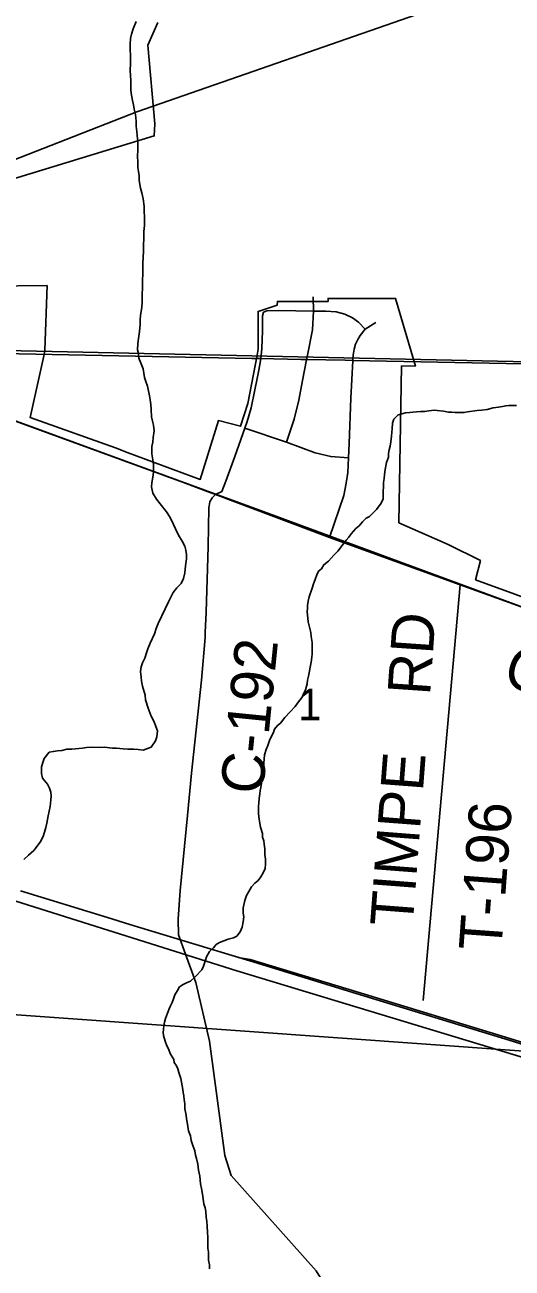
# Model space of a CAD drawing. Extents: x 36.7 to 70.7, y 0 to 22.
# Drawn here: x 40.424 to 41.074, y 18.615 to 20.274 of the extents above; entities that cross this region are included whole.
import ezdxf

# ---------------------------------------------------------------- set-up
doc = ezdxf.new("R2010")
doc.units = 0
for name, color, linetype in [('Default', 7, 'Continuous'), ('GM_X_County_Road', 7, 'Continuous'), ('GM_X_County_Road_Text', 7, 'Continuous'), ('GM_X_Minor_River', 7, 'Continuous'), ('GM_X_Rail_Line', 7, 'Continuous'), ('GM_X_Section', 7, 'Continuous'), ('GM_X_Section_Text', 7, 'Continuous'), ('GM_X_Township_Road', 7, 'Continuous'), ('GM_X_Township_Road_Text', 7, 'Continuous')]:
    doc.layers.add(name, color=color, linetype=linetype)

msp = doc.modelspace()

# ---------------------------------------------------------------- linework, layer by layer
at = {"layer": 'Default'}
for points in [[(40.6016, 20.2769), (40.5883, 20.2469), (40.5975, 20.1417), (40.5967, 20.1257), (40.3825, 20.0602)], [(40.3755, 19.9253), (40.4538, 19.9259), (40.4508, 19.8398), (40.4499, 19.8342), (40.4311, 19.7501), (40.5452, 19.7093), (40.562, 19.703), (40.6582, 19.6674), (40.6825, 19.7459), (40.7119, 19.7382), (40.7218, 19.7684), (40.7342, 19.8331), (40.7353, 19.8411), (40.7353, 19.8914), (40.761, 19.8999), (40.7612, 19.9049), (40.8013, 19.9049), (40.8288, 19.9049), (40.8288, 19.9087), (40.9188, 19.9087), (40.9452, 19.8185), (40.9268, 19.8188), (40.9232, 19.6096), (40.9888, 19.5804), (41.032, 19.5593), (41.0256, 19.5334), (41.2829, 19.4397)]]:
    msp.add_lwpolyline(points, dxfattribs=at)
at = {"layer": 'GM_X_County_Road'}
for points in [[(40.2761, 19.7943), (40.6359, 19.663), (40.6688, 19.6508)], [(40.6783, 19.6473), (40.6741, 19.6428), (40.6709, 19.6376), (40.6698, 19.6296), (40.6687, 19.5779), (40.6661, 19.4902), (40.6649, 19.4631)], [(40.6688, 19.6508), (40.6783, 19.6473), (40.8306, 19.5898)], [(40.8306, 19.5898), (41.005, 19.5265), (41.3443, 19.4045), (41.3514, 19.402)], [(40.6649, 19.4631), (40.6645, 19.4564), (40.6598, 19.3995), (40.6466, 19.2756), (40.6411, 19.2188)], [(40.6411, 19.2188), (40.6312, 19.1189), (40.6287, 19.0806), (40.6291, 19.0597), (40.6386, 19.034)], [(40.6386, 19.034), (40.6524, 18.9963), (40.6705, 18.9177), (40.6909, 18.7655), (40.6995, 18.7384), (40.8129, 18.6112), (40.8277, 18.5878), (40.8318, 18.4101)]]:
    msp.add_lwpolyline(points, dxfattribs=at)
at = {"layer": 'GM_X_Minor_River'}
for points in [[(40.5728, 20.2781), (40.5685, 20.2683), (40.5665, 20.2615), (40.5653, 20.2558), (40.5648, 20.2482), (40.5648, 20.2398), (40.5651, 20.2338), (40.5653, 20.2227), (40.5648, 20.2125), (40.5651, 20.2068), (40.5654, 20.1988), (40.5654, 20.1928), (40.5657, 20.1867), (40.5663, 20.1802), (40.5678, 20.173), (40.5692, 20.1669), (40.5699, 20.1612), (40.5717, 20.1543), (40.5728, 20.1452), (40.5727, 20.1388), (40.5734, 20.1316), (40.5741, 20.1262), (40.5748, 20.1186), (40.5747, 20.1129), (40.575, 20.1061), (40.5745, 20.0989), (40.5748, 20.0902), (40.5751, 20.0833), (40.5758, 20.078), (40.5765, 20.0723), (40.5768, 20.0662), (40.5786, 20.056), (40.5804, 20.0495), (40.5822, 20.0415), (40.5832, 20.032), (40.5835, 20.0244), (40.5838, 20.0179)], [(40.5838, 20.0179), (40.5837, 20.0062), (40.5829, 19.9982), (40.5825, 19.9705), (40.5821, 19.9648), (40.5816, 19.9546), (40.5815, 19.9417), (40.581, 19.9329), (40.5807, 19.9041), (40.5802, 19.8969), (40.5786, 19.8863), (40.5781, 19.8802), (40.578, 19.8741), (40.5772, 19.8646), (40.5759, 19.8555), (40.5751, 19.8487), (40.5746, 19.8404), (40.5757, 19.8351), (40.5764, 19.829), (40.5793, 19.8217), (40.5819, 19.8149), (40.5837, 19.8035), (40.5855, 19.7981), (40.5877, 19.7916), (40.5906, 19.7787), (40.5913, 19.7734), (40.5924, 19.7673), (40.5927, 19.7608), (40.5933, 19.751), (40.5944, 19.7449), (40.5959, 19.7396), (40.5965, 19.732), (40.5953, 19.7232), (40.5948, 19.7168), (40.5936, 19.7111), (40.5935, 19.7016), (40.595, 19.6936), (40.596, 19.6872), (40.5959, 19.6769), (40.5951, 19.6701), (40.5935, 19.6629), (40.593, 19.6576), (40.5948, 19.6488), (40.6, 19.6408), (40.6045, 19.6347), (40.6131, 19.624), (40.618, 19.6167), (40.6224, 19.6072), (40.625, 19.6014), (40.6291, 19.593), (40.6339, 19.585), (40.6376, 19.5782), (40.6391, 19.5728), (40.6398, 19.5671), (40.6397, 19.5614), (40.6385, 19.552), (40.6376, 19.5425), (40.636, 19.5353), (40.6329, 19.5285), (40.6271, 19.5228), (40.6221, 19.5164), (40.6186, 19.5093), (40.6156, 19.504), (40.6113, 19.4945), (40.602, 19.4753), (40.5992, 19.4685), (40.5972, 19.4613), (40.5914, 19.4488), (40.5883, 19.4413), (40.5863, 19.436), (40.584, 19.4288), (40.5812, 19.4227), (40.5793, 19.4171), (40.5785, 19.411), (40.5795, 19.4034), (40.5798, 19.3981), (40.5809, 19.3916), (40.5845, 19.3794), (40.5852, 19.3733), (40.5885, 19.3619), (40.5926, 19.3513), (40.5967, 19.344), (40.5989, 19.3375), (40.6011, 19.3318), (40.6002, 19.3238), (40.5983, 19.3185), (40.5925, 19.3099), (40.5818, 19.3062), (40.5754, 19.307), (40.5697, 19.3075), (40.5617, 19.3075), (40.5553, 19.308), (40.5462, 19.3089), (40.5409, 19.3089), (40.5303, 19.3102), (40.5242, 19.3095), (40.514, 19.31), (40.5064, 19.3097), (40.501, 19.3086), (40.487, 19.3072), (40.4802, 19.3073)], [(40.9743, 19.7594), (40.9701, 19.7595), (40.9633, 19.7588), (40.958, 19.7581), (40.9519, 19.7581), (40.9469, 19.7574), (40.942, 19.7571), (40.9378, 19.7568), (40.9321, 19.7561), (40.9272, 19.755), (40.9222, 19.7535), (40.9165, 19.7475), (40.9145, 19.7422), (40.9141, 19.735), (40.9136, 19.7305), (40.9132, 19.7248), (40.9123, 19.7176), (40.9115, 19.7119), (40.9103, 19.7066), (40.9095, 19.7017), (40.9091, 19.6971), (40.9067, 19.6899), (40.9047, 19.6804), (40.9039, 19.674), (40.9034, 19.6687), (40.9026, 19.663), (40.9026, 19.6588), (40.9021, 19.6501), (40.902, 19.6414), (40.8997, 19.6357), (40.8935, 19.627), (40.8885, 19.6222), (40.8839, 19.6177), (40.8797, 19.6154), (40.8747, 19.6109), (40.8701, 19.6053), (40.8659, 19.6019), (40.8597, 19.5948), (40.8563, 19.5902), (40.8528, 19.5861), (40.849, 19.5808), (40.8416, 19.5718), (40.8363, 19.5662), (40.8294, 19.5583), (40.8232, 19.5534), (40.8201, 19.5481), (40.8159, 19.5447), (40.8136, 19.5398), (40.8113, 19.5338), (40.8093, 19.5281), (40.8073, 19.5221), (40.8034, 19.5107), (40.8022, 19.505), (40.8014, 19.4993), (40.8013, 19.4952), (40.8009, 19.491), (40.8012, 19.4864), (40.8016, 19.4823), (40.8023, 19.4773), (40.8041, 19.4701), (40.8055, 19.4629), (40.8062, 19.4579), (40.8073, 19.4496), (40.8076, 19.4454), (40.8075, 19.4344), (40.807, 19.4302), (40.8062, 19.4234), (40.805, 19.4169), (40.8034, 19.4094), (40.8026, 19.4048), (40.8014, 19.3995), (40.8006, 19.3946), (40.7986, 19.3866), (40.7962, 19.3817), (40.7943, 19.3768), (40.7878, 19.3689), (40.7847, 19.3644), (40.7781, 19.3572), (40.7712, 19.3497), (40.7654, 19.3422), (40.7612, 19.3392), (40.7574, 19.3343), (40.7558, 19.3298), (40.7535, 19.3256), (40.7504, 19.3192), (40.7484, 19.3124), (40.7461, 19.3071), (40.7441, 19.2999), (40.7433, 19.2942), (40.7428, 19.2893), (40.7424, 19.2825), (40.7416, 19.2779), (40.7407, 19.2719), (40.7403, 19.2677), (40.7399, 19.262), (40.7391, 19.2563), (40.7382, 19.2521), (40.7378, 19.248), (40.7366, 19.2415), (40.7365, 19.2358), (40.7357, 19.2313)], [(41.0802, 19.7659), (41.0699, 19.766), (41.0658, 19.7657), (41.0612, 19.7646), (41.0563, 19.7639), (41.049, 19.7628), (41.0411, 19.7606), (41.0335, 19.7599), (41.0278, 19.7592), (41.0148, 19.7575), (41.0099, 19.7564), (40.9981, 19.7565), (40.9936, 19.7569), (40.9894, 19.757), (40.9826, 19.7582), (40.9743, 19.7594)], [(40.4802, 19.3073), (40.4733, 19.3058), (40.4676, 19.3051), (40.4623, 19.3044), (40.4566, 19.3034), (40.4501, 19.2951), (40.4481, 19.2898), (40.4465, 19.2837), (40.4464, 19.275), (40.4475, 19.2689), (40.4542, 19.2609), (40.4572, 19.2555), (40.459, 19.2502), (40.4594, 19.2449), (40.4589, 19.2396), (40.4577, 19.2308), (40.4553, 19.2183), (40.4536, 19.2085), (40.452, 19.2028), (40.4505, 19.1968), (40.4485, 19.1907), (40.4446, 19.1835), (40.4361, 19.1722), (40.4292, 19.1662), (40.4227, 19.1602)], [(40.7357, 19.2313), (40.7357, 19.2267), (40.736, 19.2222), (40.7363, 19.2172), (40.7377, 19.2081), (40.7384, 19.2032), (40.741, 19.1948), (40.7413, 19.1902), (40.7432, 19.1849), (40.7435, 19.1807), (40.7442, 19.1743), (40.7445, 19.1667), (40.7452, 19.1606), (40.7451, 19.1545), (40.7446, 19.1484), (40.7419, 19.1424), (40.7388, 19.1371), (40.7354, 19.1322), (40.7312, 19.1288), (40.7265, 19.1236), (40.7231, 19.1175), (40.72, 19.1123), (40.7176, 19.1055), (40.7168, 19.1013), (40.7156, 19.0956), (40.7155, 19.0888), (40.7162, 19.0835), (40.7154, 19.077), (40.7142, 19.0698), (40.7114, 19.0638), (40.7068, 19.0581), (40.7026, 19.0559), (40.6954, 19.0537), (40.6897, 19.0515), (40.684, 19.0496), (40.6794, 19.0466), (40.6759, 19.0425), (40.6706, 19.0373), (40.6667, 19.0305), (40.6651, 19.0259), (40.6627, 19.018), (40.6604, 19.0131), (40.652, 19.004), (40.6451, 18.998), (40.6405, 18.9962), (40.6355, 18.9936), (40.6306, 18.9902), (40.6279, 18.9853), (40.6244, 18.9797), (40.6224, 18.9744), (40.6208, 18.9695), (40.6174, 18.963), (40.6146, 18.9551), (40.6119, 18.9479), (40.6103, 18.943), (40.6095, 18.9388), (40.6091, 18.9335), (40.6086, 18.9294), (40.609, 18.9252), (40.6112, 18.9179), (40.6134, 18.9118), (40.6156, 18.9076), (40.6178, 18.9012), (40.623, 18.8935), (40.6233, 18.8893), (40.6263, 18.8851), (40.6282, 18.8809), (40.6296, 18.876), (40.6322, 18.868), (40.6333, 18.863), (40.634, 18.8581), (40.6347, 18.8535), (40.6354, 18.8494), (40.6361, 18.8448), (40.6368, 18.8395), (40.6375, 18.8345), (40.6378, 18.8277), (40.6392, 18.8193), (40.6399, 18.8144), (40.6406, 18.8098), (40.6424, 18.798), (40.645, 18.7916), (40.6461, 18.7855), (40.6483, 18.7786), (40.6508, 18.7714), (40.6519, 18.7657), (40.653, 18.7611), (40.6548, 18.7539), (40.6559, 18.7459), (40.6577, 18.7375), (40.6587, 18.7273), (40.6597, 18.7212), (40.6612, 18.7139), (40.6629, 18.7006), (40.6648, 18.6953), (40.6655, 18.6907), (40.6661, 18.6828), (40.6668, 18.6774), (40.6675, 18.671), (40.6678, 18.6626), (40.6681, 18.6562)], [(40.6681, 18.6562), (40.6681, 18.652), (40.6683, 18.6418), (40.669, 18.6361), (40.6693, 18.6258), (40.6703, 18.6193), (40.6703, 18.614)]]:
    msp.add_lwpolyline(points, dxfattribs=at)
at = {"layer": 'GM_X_Rail_Line'}
for points in [[(39.9505, 19.9142), (40.5737, 20.1578), (40.9777, 20.2985), (41.2372, 20.3864), (41.8047, 20.6015), (42.0399, 20.6949), (42.6066, 20.8969)], [(39.9505, 19.9142), (40.2796, 19.7934), (40.742, 19.6245), (41.298, 19.4193), (41.8828, 19.2032), (42.4402, 19.0032), (43.0913, 18.7734), (43.6618, 18.5644), (44.5563, 18.22), (44.9526, 18.0665), (45.405, 17.9057), (45.5934, 17.8393)], [(39.4351, 19.5275), (39.5072, 19.4857), (39.6526, 19.4084), (39.8435, 19.3143), (39.9823, 19.2538), (40.1053, 19.2054), (40.2394, 19.1588), (40.707, 19.0117), (41.5752, 18.749), (42.4154, 18.492), (43.2547, 18.2349), (44.5058, 17.8517), (44.9515, 17.7199), (45.506, 17.5551), (45.5934, 17.5283)], [(40.4184, 19.1184), (40.5342, 19.0828), (40.5644, 19.0736), (40.633, 19.0526), (40.7242, 19.0248), (40.8662, 18.9816), (41.0703, 18.9191), (41.1118, 18.9063), (41.2352, 18.8682), (41.3301, 18.8394), (41.5595, 18.7692), (41.7245, 18.7187), (41.8299, 18.6867), (41.9106, 18.662), (41.99, 18.6377), (42.0947, 18.6058), (42.1775, 18.5805), (42.2523, 18.5576), (42.4612, 18.4939)], [(40.7086, 19.0296), (40.7249, 19.027), (40.8669, 18.9838), (41.071, 18.9213), (41.1125, 18.9085), (41.2359, 18.8705), (41.3307, 18.8416), (41.5602, 18.7714), (41.7252, 18.7209), (41.8306, 18.6889), (41.9112, 18.6642), (41.9461, 18.6535), (41.9703, 18.6437)]]:
    msp.add_lwpolyline(points, dxfattribs=at)
at = {"layer": 'GM_X_Section'}
for points in [[(41.3712, 20.8297), (41.3719, 20.8169), (41.3623, 19.8182), (40.3573, 19.8404), (40.3846, 20.8226)], [(40.2724, 19.8432), (40.3573, 19.8404), (41.3623, 19.8182), (41.3264, 18.9176), (41.3255, 18.8876), (40.2272, 18.9664)], [(41.3255, 18.8876), (41.2819, 17.9105), (41.2806, 17.8858), (40.1915, 17.9066), (40.2272, 18.9664)]]:
    msp.add_lwpolyline(points, close=True, dxfattribs=at)
at = {"layer": 'GM_X_Township_Road'}
msp.add_line((40.9554, 18.9721), (41.005, 19.5265), dxfattribs=at)
for points in [[(40.1721, 19.8397), (40.7272, 19.8287), (40.7387, 19.8285), (40.7924, 19.8275), (40.7997, 19.8273), (40.8514, 19.8263), (40.8614, 19.8261), (41.3623, 19.8162), (41.3626, 19.8228), (41.3628, 19.8405), (41.3629, 19.8535), (41.3659, 20.06), (41.3665, 20.1284), (41.3664, 20.1389), (41.3664, 20.1643), (41.3664, 20.1648), (41.3661, 20.3009), (41.3748, 20.8969), (38.7934, 20.8969)], [(40.7999, 19.8268), (40.8012, 19.8332), (40.8077, 19.8671), (40.8091, 19.8919), (40.809, 19.911)], [(40.7335, 19.7996), (40.7362, 19.8132), (40.7389, 19.828), (40.7405, 19.8422), (40.741, 19.8654), (40.7411, 19.8857), (40.7426, 19.8904)], [(40.7426, 19.8904), (40.7472, 19.8923), (40.7622, 19.8926), (40.8091, 19.8919), (40.8259, 19.8916), (40.8395, 19.8909), (40.8509, 19.888), (40.8611, 19.883), (40.8691, 19.8769), (40.8782, 19.8679)], [(40.8618, 19.8284), (40.8621, 19.8332), (40.8633, 19.8409), (40.8655, 19.8478), (40.8682, 19.8538), (40.8714, 19.8592), (40.8782, 19.8679), (40.8923, 19.8768)], [(41.1522, 14.4699), (41.174, 14.9671), (41.1745, 14.977), (41.2392, 16.3776), (41.2409, 16.4152), (41.2499, 16.8815), (41.2661, 17.5372), (41.3022, 18.3874), (41.3025, 18.3936), (41.3037, 18.4227), (41.344, 19.4017), (41.3441, 19.4051), (41.3623, 19.8162), (40.8614, 19.8261), (40.8514, 19.8263), (40.7997, 19.8273), (40.7924, 19.8275), (40.7387, 19.8285), (40.7272, 19.8287), (40.1721, 19.8397)], [(40.7733, 19.7171), (40.7834, 19.7479), (40.7895, 19.7732), (40.7946, 19.7994), (40.7999, 19.8268)], [(40.8306, 19.5898), (40.8497, 19.6457), (40.853, 19.6622), (40.855, 19.6764), (40.8558, 19.6961), (40.8567, 19.7151), (40.8592, 19.7758), (40.8617, 19.8255), (40.8618, 19.8284)], [(40.6783, 19.6473), (40.6871, 19.6514), (40.6921, 19.6648), (40.7041, 19.6981), (40.7177, 19.7359), (40.7206, 19.7445), (40.726, 19.7627), (40.731, 19.7869), (40.7335, 19.7996)], [(40.7177, 19.7359), (40.7733, 19.7171), (40.8115, 19.7028), (40.8322, 19.6978), (40.8558, 19.6961)]]:
    msp.add_lwpolyline(points, dxfattribs=at)

# ---------------------------------------------------------------- texts
at = {"layer": 'GM_X_County_Road_Text'}
for s, rotation, p in [('C-192', 84.2806, (40.7414, 19.2458)), ('C-20', 341.1304, (41.0594, 19.3951))]:
    msp.add_text(s, height=0.05682, rotation=rotation, dxfattribs=at).set_placement(p)
at = {"layer": 'GM_X_Section_Text'}
msp.add_text('1', height=0.0419, rotation=0, dxfattribs=at).set_placement((40.7888, 19.3461))
at = {"layer": 'GM_X_Township_Road_Text'}
for s, rotation, p in [('RD', 86.0551, (40.9647, 19.3783)), ('TIMPE', 85.6371, (40.9414, 19.0693)), ('T-196', 85.7948, (41.0597, 19.0371))]:
    msp.add_text(s, height=0.05682, rotation=rotation, dxfattribs=at).set_placement(p)

doc.saveas('drawing.dxf')
